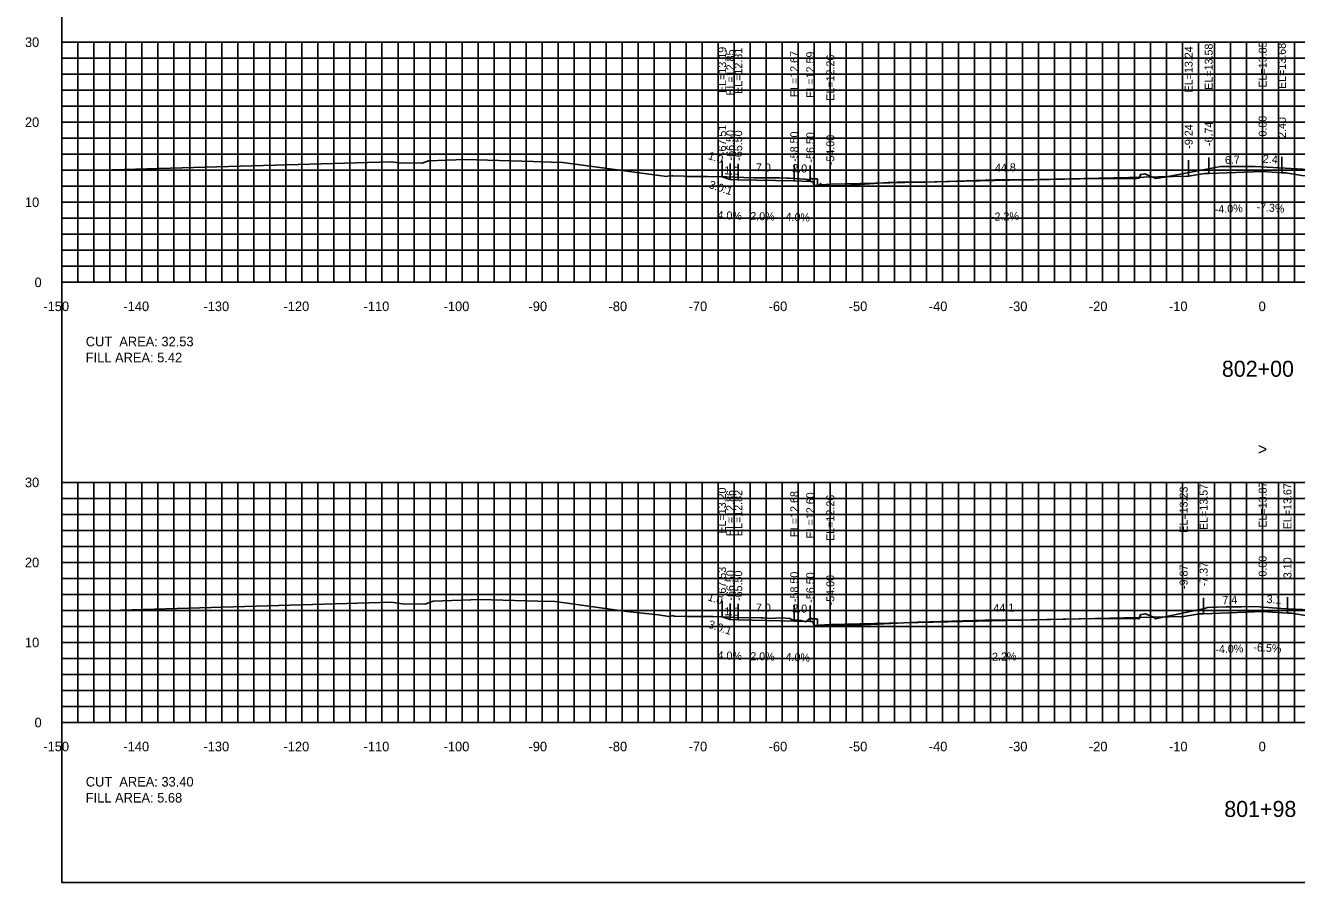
# Model space of a CAD drawing. Extents: x 1797419 to 1809236, y 248759 to 251512.
# Drawn here: x 1802476.5 to 1802635.2, y 250854.9 to 250962 of the extents above; entities that cross this region are included whole.
import ezdxf

# ---------------------------------------------------------------- set-up
doc = ezdxf.new("R2010")
doc.units = 0
for name, color, linetype in [('1', 7, 'Continuous'), ('10', 7, 'Continuous'), ('3', 7, 'Continuous'), ('31', 7, 'Continuous'), ('4', 7, 'Continuous'), ('60', 7, 'Continuous'), ('ANNO-TXT', 7, 'Continuous'), ('CL-CNST', 7, 'Continuous'), ('Level 62', 7, 'Continuous'), ('M-ROADS', 7, 'Continuous')]:
    doc.layers.add(name, color=color, linetype=linetype)

msp = doc.modelspace()

# ---------------------------------------------------------------- linework, layer by layer
for p, q in [((1802563.49, 250943.08), (1802563.49, 250945.08)), ((1802564.5, 250942.74), (1802564.5, 250944.74)), ((1802565.5, 250942.7), (1802565.5, 250944.7)), ((1802621.76, 250943.13), (1802621.76, 250945.13)), ((1802624.26, 250943.47), (1802624.26, 250945.47)), ((1802631, 250943.74), (1802631, 250945.74)), ((1802633.4, 250943.57), (1802633.4, 250945.57)), ((1802572.5, 250942.56), (1802572.5, 250944.56)), ((1802574.5, 250942.48), (1802574.5, 250944.48)), ((1802577, 250942.15), (1802577, 250944.15)), ((1802631, 250888.76), (1802631, 250890.76)), ((1802563.47, 250888.09), (1802563.47, 250890.09)), ((1802564.5, 250887.75), (1802564.5, 250889.75)), ((1802565.5, 250887.71), (1802565.5, 250889.71)), ((1802572.5, 250887.57), (1802572.5, 250889.57)), ((1802574.5, 250887.49), (1802574.5, 250889.49)), ((1802577, 250887.15), (1802577, 250889.15)), ((1802623.63, 250888.46), (1802623.63, 250890.46)), ((1802634.1, 250888.56), (1802634.1, 250890.56))]:
    msp.add_line(p, q)
msp.add_lwpolyline([(1802481, 250854.89), (1802781, 250854.89), (1802781, 251044.89), (1802481, 251044.89)], close=True)
at = {"layer": '60'}
for p, q in [((1802480.94, 250959.89), (1802481, 250959.89)), ((1802481, 250929.89), (1802481, 250959.89)), ((1802480.94, 250949.89), (1802481, 250949.89)), ((1802480.94, 250939.89), (1802481, 250939.89)), ((1802480.94, 250929.89), (1802481, 250929.89)), ((1802481, 250929.89), (1802781, 250929.89)), ((1802481, 250929.83), (1802481, 250929.89)), ((1802491, 250929.83), (1802491, 250929.89)), ((1802501, 250929.83), (1802501, 250929.89)), ((1802511, 250929.83), (1802511, 250929.89)), ((1802521, 250929.83), (1802521, 250929.89)), ((1802531, 250929.83), (1802531, 250929.89)), ((1802541, 250929.83), (1802541, 250929.89)), ((1802551, 250929.83), (1802551, 250929.89)), ((1802561, 250929.83), (1802561, 250929.89)), ((1802571, 250929.83), (1802571, 250929.89)), ((1802581, 250929.83), (1802581, 250929.89)), ((1802591, 250929.83), (1802591, 250929.89)), ((1802601, 250929.83), (1802601, 250929.89)), ((1802611, 250929.83), (1802611, 250929.89)), ((1802621, 250929.83), (1802621, 250929.89)), ((1802631, 250929.83), (1802631, 250929.89)), ((1802480.94, 250904.89), (1802481, 250904.89)), ((1802481, 250874.89), (1802481, 250904.89)), ((1802480.94, 250894.89), (1802481, 250894.89)), ((1802480.94, 250884.89), (1802481, 250884.89)), ((1802480.94, 250874.89), (1802481, 250874.89)), ((1802481, 250874.89), (1802781, 250874.89)), ((1802481, 250874.83), (1802481, 250874.89)), ((1802491, 250874.83), (1802491, 250874.89)), ((1802501, 250874.83), (1802501, 250874.89)), ((1802511, 250874.83), (1802511, 250874.89)), ((1802521, 250874.83), (1802521, 250874.89)), ((1802531, 250874.83), (1802531, 250874.89)), ((1802541, 250874.83), (1802541, 250874.89)), ((1802551, 250874.83), (1802551, 250874.89)), ((1802561, 250874.83), (1802561, 250874.89)), ((1802571, 250874.83), (1802571, 250874.89)), ((1802581, 250874.83), (1802581, 250874.89)), ((1802591, 250874.83), (1802591, 250874.89)), ((1802601, 250874.83), (1802601, 250874.89)), ((1802611, 250874.83), (1802611, 250874.89)), ((1802621, 250874.83), (1802621, 250874.89)), ((1802631, 250874.83), (1802631, 250874.89))]:
    msp.add_line(p, q, dxfattribs=at)
at = {"layer": 'CL-CNST'}
for points in [[(1802563.49, 250943.08), (1802564.5, 250942.74), (1802565.5, 250942.7), (1802572.5, 250942.56), (1802574.5, 250942.48), (1802574.83, 250942.48), (1802575, 250941.98), (1802577, 250942.15), (1802621.76, 250943.13), (1802623.76, 250943.47), (1802624.26, 250943.47), (1802631, 250943.74), (1802633.4, 250943.57), (1802633.9, 250943.57), (1802635.9, 250943.23), (1802697, 250941.88), (1802699, 250941.72), (1802699.17, 250942.22), (1802699.5, 250942.22), (1802701.5, 250942.3), (1802706.5, 250942.4), (1802707.5, 250942.44), (1802709.18, 250943)], [(1802563.47, 250888.09), (1802564.5, 250887.75), (1802565.5, 250887.71), (1802572.5, 250887.57), (1802574.5, 250887.49), (1802574.83, 250887.49), (1802575, 250886.99), (1802577, 250887.15), (1802621.13, 250888.12), (1802623.13, 250888.46), (1802623.63, 250888.46), (1802631, 250888.76), (1802634.1, 250888.56), (1802634.6, 250888.56), (1802636.6, 250888.22), (1802697, 250886.89), (1802699, 250886.72), (1802699.17, 250887.22), (1802699.5, 250887.22), (1802701.5, 250887.3), (1802706.5, 250887.4), (1802707.5, 250887.44), (1802709.18, 250888.01)]]:
    msp.add_lwpolyline(points, dxfattribs=at)
at = {"layer": 'Level 62'}
for p, q in [((1802481, 250959.89), (1802781, 250959.89)), ((1802481, 250929.89), (1802481, 250959.89)), ((1802483, 250929.89), (1802483, 250959.89)), ((1802485, 250929.89), (1802485, 250959.89)), ((1802487, 250929.89), (1802487, 250959.89)), ((1802489, 250929.89), (1802489, 250959.89)), ((1802491, 250929.89), (1802491, 250959.89)), ((1802493, 250929.89), (1802493, 250959.89)), ((1802495, 250929.89), (1802495, 250959.89)), ((1802497, 250929.89), (1802497, 250959.89)), ((1802499, 250929.89), (1802499, 250959.89)), ((1802501, 250929.89), (1802501, 250959.89)), ((1802503, 250929.89), (1802503, 250959.89)), ((1802505, 250929.89), (1802505, 250959.89)), ((1802507, 250929.89), (1802507, 250959.89)), ((1802509, 250929.89), (1802509, 250959.89)), ((1802511, 250929.89), (1802511, 250959.89)), ((1802513, 250929.89), (1802513, 250959.89)), ((1802515, 250929.89), (1802515, 250959.89)), ((1802517, 250929.89), (1802517, 250959.89)), ((1802519, 250929.89), (1802519, 250959.89)), ((1802521, 250929.89), (1802521, 250959.89)), ((1802523, 250929.89), (1802523, 250959.89)), ((1802525, 250929.89), (1802525, 250959.89)), ((1802527, 250929.89), (1802527, 250959.89)), ((1802529, 250929.89), (1802529, 250959.89)), ((1802531, 250929.89), (1802531, 250959.89)), ((1802533, 250929.89), (1802533, 250959.89)), ((1802535, 250929.89), (1802535, 250959.89)), ((1802537, 250929.89), (1802537, 250959.89)), ((1802539, 250929.89), (1802539, 250959.89)), ((1802541, 250929.89), (1802541, 250959.89)), ((1802543, 250929.89), (1802543, 250959.89)), ((1802545, 250929.89), (1802545, 250959.89)), ((1802547, 250929.89), (1802547, 250959.89)), ((1802549, 250929.89), (1802549, 250959.89)), ((1802551, 250929.89), (1802551, 250959.89)), ((1802553, 250929.89), (1802553, 250959.89)), ((1802555, 250929.89), (1802555, 250959.89)), ((1802557, 250929.89), (1802557, 250959.89)), ((1802559, 250929.89), (1802559, 250959.89)), ((1802561, 250929.89), (1802561, 250959.89)), ((1802563, 250929.89), (1802563, 250959.89)), ((1802565, 250929.89), (1802565, 250959.89)), ((1802567, 250929.89), (1802567, 250959.89)), ((1802569, 250929.89), (1802569, 250959.89)), ((1802571, 250929.89), (1802571, 250959.89)), ((1802573, 250929.89), (1802573, 250959.89)), ((1802575, 250929.89), (1802575, 250959.89)), ((1802577, 250929.89), (1802577, 250959.89)), ((1802579, 250929.89), (1802579, 250959.89)), ((1802581, 250929.89), (1802581, 250959.89)), ((1802583, 250929.89), (1802583, 250959.89)), ((1802585, 250929.89), (1802585, 250959.89)), ((1802587, 250929.89), (1802587, 250959.89)), ((1802589, 250929.89), (1802589, 250959.89)), ((1802591, 250929.89), (1802591, 250959.89)), ((1802593, 250929.89), (1802593, 250959.89)), ((1802595, 250929.89), (1802595, 250959.89)), ((1802597, 250929.89), (1802597, 250959.89)), ((1802599, 250929.89), (1802599, 250959.89)), ((1802601, 250929.89), (1802601, 250959.89)), ((1802603, 250929.89), (1802603, 250959.89)), ((1802605, 250929.89), (1802605, 250959.89)), ((1802607, 250929.89), (1802607, 250959.89)), ((1802609, 250929.89), (1802609, 250959.89)), ((1802611, 250929.89), (1802611, 250959.89)), ((1802613, 250929.89), (1802613, 250959.89)), ((1802615, 250929.89), (1802615, 250959.89)), ((1802617, 250929.89), (1802617, 250959.89)), ((1802619, 250929.89), (1802619, 250959.89)), ((1802621, 250929.89), (1802621, 250959.89)), ((1802623, 250929.89), (1802623, 250959.89)), ((1802625, 250929.89), (1802625, 250959.89)), ((1802627, 250929.89), (1802627, 250959.89)), ((1802629, 250929.89), (1802629, 250959.89)), ((1802631, 250929.89), (1802631, 250959.89)), ((1802633, 250929.89), (1802633, 250959.89)), ((1802635, 250929.89), (1802635, 250959.89)), ((1802481, 250957.89), (1802781, 250957.89)), ((1802481, 250955.89), (1802781, 250955.89)), ((1802481, 250953.89), (1802781, 250953.89)), ((1802481, 250951.89), (1802781, 250951.89)), ((1802481, 250949.89), (1802781, 250949.89)), ((1802481, 250947.89), (1802781, 250947.89)), ((1802481, 250945.89), (1802781, 250945.89)), ((1802481, 250943.89), (1802781, 250943.89)), ((1802481, 250941.89), (1802781, 250941.89)), ((1802481, 250939.89), (1802781, 250939.89)), ((1802481, 250937.89), (1802781, 250937.89)), ((1802481, 250935.89), (1802781, 250935.89)), ((1802481, 250933.89), (1802781, 250933.89)), ((1802481, 250931.89), (1802781, 250931.89)), ((1802481, 250929.89), (1802781, 250929.89)), ((1802481, 250904.89), (1802781, 250904.89)), ((1802481, 250874.89), (1802481, 250904.89)), ((1802483, 250874.89), (1802483, 250904.89)), ((1802485, 250874.89), (1802485, 250904.89)), ((1802487, 250874.89), (1802487, 250904.89)), ((1802489, 250874.89), (1802489, 250904.89)), ((1802491, 250874.89), (1802491, 250904.89)), ((1802493, 250874.89), (1802493, 250904.89)), ((1802495, 250874.89), (1802495, 250904.89)), ((1802497, 250874.89), (1802497, 250904.89)), ((1802499, 250874.89), (1802499, 250904.89)), ((1802501, 250874.89), (1802501, 250904.89)), ((1802503, 250874.89), (1802503, 250904.89)), ((1802505, 250874.89), (1802505, 250904.89)), ((1802507, 250874.89), (1802507, 250904.89)), ((1802509, 250874.89), (1802509, 250904.89)), ((1802511, 250874.89), (1802511, 250904.89)), ((1802513, 250874.89), (1802513, 250904.89)), ((1802515, 250874.89), (1802515, 250904.89)), ((1802517, 250874.89), (1802517, 250904.89)), ((1802519, 250874.89), (1802519, 250904.89)), ((1802521, 250874.89), (1802521, 250904.89)), ((1802523, 250874.89), (1802523, 250904.89)), ((1802525, 250874.89), (1802525, 250904.89)), ((1802527, 250874.89), (1802527, 250904.89)), ((1802529, 250874.89), (1802529, 250904.89)), ((1802531, 250874.89), (1802531, 250904.89)), ((1802533, 250874.89), (1802533, 250904.89)), ((1802535, 250874.89), (1802535, 250904.89)), ((1802537, 250874.89), (1802537, 250904.89)), ((1802539, 250874.89), (1802539, 250904.89)), ((1802541, 250874.89), (1802541, 250904.89)), ((1802543, 250874.89), (1802543, 250904.89)), ((1802545, 250874.89), (1802545, 250904.89)), ((1802547, 250874.89), (1802547, 250904.89)), ((1802549, 250874.89), (1802549, 250904.89)), ((1802551, 250874.89), (1802551, 250904.89)), ((1802553, 250874.89), (1802553, 250904.89)), ((1802555, 250874.89), (1802555, 250904.89)), ((1802557, 250874.89), (1802557, 250904.89)), ((1802559, 250874.89), (1802559, 250904.89)), ((1802561, 250874.89), (1802561, 250904.89)), ((1802563, 250874.89), (1802563, 250904.89)), ((1802565, 250874.89), (1802565, 250904.89)), ((1802567, 250874.89), (1802567, 250904.89)), ((1802569, 250874.89), (1802569, 250904.89)), ((1802571, 250874.89), (1802571, 250904.89)), ((1802573, 250874.89), (1802573, 250904.89)), ((1802575, 250874.89), (1802575, 250904.89)), ((1802577, 250874.89), (1802577, 250904.89)), ((1802579, 250874.89), (1802579, 250904.89)), ((1802581, 250874.89), (1802581, 250904.89)), ((1802583, 250874.89), (1802583, 250904.89)), ((1802585, 250874.89), (1802585, 250904.89)), ((1802587, 250874.89), (1802587, 250904.89)), ((1802589, 250874.89), (1802589, 250904.89)), ((1802591, 250874.89), (1802591, 250904.89)), ((1802593, 250874.89), (1802593, 250904.89)), ((1802595, 250874.89), (1802595, 250904.89)), ((1802597, 250874.89), (1802597, 250904.89)), ((1802599, 250874.89), (1802599, 250904.89)), ((1802601, 250874.89), (1802601, 250904.89)), ((1802603, 250874.89), (1802603, 250904.89)), ((1802605, 250874.89), (1802605, 250904.89)), ((1802607, 250874.89), (1802607, 250904.89)), ((1802609, 250874.89), (1802609, 250904.89)), ((1802611, 250874.89), (1802611, 250904.89)), ((1802613, 250874.89), (1802613, 250904.89)), ((1802615, 250874.89), (1802615, 250904.89)), ((1802617, 250874.89), (1802617, 250904.89)), ((1802619, 250874.89), (1802619, 250904.89)), ((1802621, 250874.89), (1802621, 250904.89)), ((1802623, 250874.89), (1802623, 250904.89)), ((1802625, 250874.89), (1802625, 250904.89)), ((1802627, 250874.89), (1802627, 250904.89)), ((1802629, 250874.89), (1802629, 250904.89)), ((1802631, 250874.89), (1802631, 250904.89)), ((1802633, 250874.89), (1802633, 250904.89)), ((1802635, 250874.89), (1802635, 250904.89)), ((1802481, 250902.89), (1802781, 250902.89)), ((1802481, 250900.89), (1802781, 250900.89)), ((1802481, 250898.89), (1802781, 250898.89)), ((1802481, 250896.89), (1802781, 250896.89)), ((1802481, 250894.89), (1802781, 250894.89)), ((1802481, 250892.89), (1802781, 250892.89)), ((1802481, 250890.89), (1802781, 250890.89)), ((1802481, 250888.89), (1802781, 250888.89)), ((1802481, 250886.89), (1802781, 250886.89)), ((1802481, 250884.89), (1802781, 250884.89)), ((1802481, 250882.89), (1802781, 250882.89)), ((1802481, 250880.89), (1802781, 250880.89)), ((1802481, 250878.89), (1802781, 250878.89)), ((1802481, 250876.89), (1802781, 250876.89)), ((1802481, 250874.89), (1802781, 250874.89))]:
    msp.add_line(p, q, dxfattribs=at)
at = {"layer": 'M-ROADS'}
for points in [[(1802484.41, 250943.84), (1802522.14, 250944.95), (1802523.48, 250944.77), (1802525.11, 250944.82), (1802526, 250944.77), (1802526.8, 250945.07), (1802531.39, 250945.24), (1802539.9, 250944.98), (1802542.16, 250944.91), (1802543.57, 250944.87), (1802555.63, 250943.22), (1802556.24, 250943.16), (1802556.45, 250943.12), (1802557.07, 250943.25), (1802557.16, 250943.17), (1802557.21, 250943.19), (1802557.25, 250943.19), (1802557.31, 250943.19), (1802558.74, 250943.13), (1802558.96, 250943.12), (1802560.46, 250943.12), (1802561.66, 250943.12), (1802564.07, 250943.07), (1802564.89, 250943.01), (1802567.48, 250942.95), (1802568.09, 250942.95), (1802570.33, 250942.95), (1802570.44, 250942.94), (1802570.59, 250942.95), (1802571.53, 250942.9), (1802571.65, 250942.89), (1802571.85, 250942.9), (1802573.79, 250942.78), (1802574.05, 250942.72), (1802574.08, 250942.77), (1802574.3, 250942.62), (1802574.33, 250942.71), (1802574.35, 250942.73), (1802574.37, 250942.76), (1802574.38, 250942.79), (1802574.39, 250942.8), (1802574.39, 250942.8), (1802574.4, 250942.82), (1802574.4, 250942.82), (1802574.41, 250942.83), (1802574.41, 250942.83), (1802574.42, 250942.83), (1802574.45, 250942.88), (1802574.73, 250942.85), (1802574.77, 250942.77), (1802574.89, 250942.83), (1802575.34, 250942.82), (1802575.39, 250942.69), (1802575.39, 250941.97), (1802575.39, 250941.97), (1802575.4, 250941.97), (1802575.42, 250941.97), (1802575.5, 250941.96), (1802575.78, 250942.25), (1802575.85, 250941.96), (1802576.85, 250941.95), (1802578.37, 250941.96), (1802584.22, 250942.35), (1802585.37, 250942.4), (1802587.5, 250942.4), (1802589.1, 250942.4), (1802594.03, 250942.57), (1802597.58, 250942.69), (1802599.43, 250942.69), (1802601.92, 250942.69), (1802601.98, 250942.69), (1802602.38, 250942.7), (1802610.17, 250942.87), (1802611.61, 250942.88), (1802612.4, 250942.88), (1802612.58, 250942.88), (1802612.89, 250942.86), (1802612.97, 250942.86), (1802614.05, 250942.87), (1802614.49, 250942.87), (1802615.02, 250942.87), (1802615.09, 250942.87), (1802615.11, 250942.88), (1802615.12, 250942.98), (1802615.12, 250942.88), (1802615.12, 250942.87), (1802615.13, 250942.87), (1802615.13, 250942.88), (1802615.14, 250942.88), (1802615.24, 250942.86), (1802615.58, 250942.92), (1802615.73, 250943.37), (1802615.8, 250943.37), (1802615.81, 250943.3), (1802615.81, 250943.36), (1802615.82, 250943.33), (1802615.89, 250943.36), (1802616.29, 250943.44), (1802617.67, 250942.86), (1802618.73, 250943.02), (1802625.75, 250944.36), (1802627.21, 250944.36), (1802629.15, 250944.36), (1802630.05, 250944.35), (1802639.01, 250943.86)], [(1802486.96, 250888.87), (1802522.2, 250889.91), (1802523.83, 250889.68), (1802525.21, 250889.72), (1802526.36, 250889.67), (1802527.38, 250890.04), (1802533.27, 250890.27), (1802538.95, 250890.09), (1802540.46, 250890.05), (1802542.63, 250889.99), (1802551.6, 250888.76), (1802555.52, 250888.35), (1802556.84, 250888.14), (1802557.35, 250888.24), (1802557.43, 250888.18), (1802557.47, 250888.19), (1802557.51, 250888.19), (1802557.56, 250888.19), (1802559.18, 250888.12), (1802559.58, 250888.12), (1802562.36, 250888.12), (1802564.34, 250888.07), (1802565.01, 250888.03), (1802568.37, 250887.95), (1802568.41, 250887.95), (1802568.55, 250887.95), (1802569.56, 250887.89), (1802570.15, 250887.92), (1802570.93, 250887.95), (1802571.91, 250887.89), (1802571.99, 250887.89), (1802572.16, 250887.76), (1802573.34, 250887.62), (1802573.93, 250887.45), (1802574.05, 250887.59), (1802574.46, 250887.89), (1802574.73, 250887.87), (1802574.77, 250887.8), (1802574.87, 250887.85), (1802575.35, 250887.84), (1802575.39, 250887.73), (1802575.39, 250887.1), (1802575.64, 250886.97), (1802577.71, 250886.97), (1802578.03, 250886.97), (1802578.24, 250886.97), (1802579.05, 250887.02), (1802582, 250887.14), (1802587.89, 250887.41), (1802588.01, 250887.41), (1802596.34, 250887.68), (1802597.61, 250887.71), (1802599.19, 250887.69), (1802599.77, 250887.69), (1802600.21, 250887.69), (1802602.09, 250887.73), (1802608.1, 250887.84), (1802610.19, 250887.88), (1802612.15, 250887.89), (1802612.39, 250887.89), (1802612.78, 250887.88), (1802613, 250887.87), (1802613.44, 250887.87), (1802614.86, 250887.86), (1802615.05, 250887.86), (1802615.11, 250887.89), (1802615.12, 250887.97), (1802615.12, 250887.89), (1802615.12, 250887.89), (1802615.13, 250887.88), (1802615.15, 250887.89), (1802615.16, 250887.89), (1802615.48, 250887.85), (1802615.58, 250887.86), (1802615.75, 250888.38), (1802615.8, 250888.38), (1802615.81, 250888.33), (1802615.81, 250888.37), (1802615.82, 250888.35), (1802615.88, 250888.37), (1802616.35, 250888.47), (1802617.36, 250888.04), (1802617.62, 250887.85), (1802623.72, 250889.13), (1802624.13, 250889.25), (1802626.43, 250889.36), (1802627.55, 250889.36), (1802628.39, 250889.36), (1802630.06, 250889.37), (1802633.31, 250889.13), (1802636.88, 250888.96)]]:
    msp.add_lwpolyline(points, dxfattribs=at)

# ---------------------------------------------------------------- texts
for p in [(1802561.75, 250941.7), (1802561.67, 250886.76)]:
    msp.add_text('3.0:1', height=1, rotation=341.5651).set_placement(p)
at = {"layer": '1'}
for s, p in [('802+00', (1802625.91, 250918.09)), ('801+98', (1802626.21, 250863.09))]:
    msp.add_text(s, height=2, dxfattribs=at).set_placement(p)
at = {"layer": '10'}
for s, p in [('-150', (1802478.7, 250926.29)), ('-140', (1802488.7, 250926.29)), ('-130', (1802498.7, 250926.29)), ('-120', (1802508.7, 250926.29)), ('-110', (1802518.7, 250926.29)), ('-100', (1802528.7, 250926.29)), ('-90', (1802539.3, 250926.29)), ('-80', (1802549.3, 250926.29)), ('-70', (1802559.3, 250926.29)), ('-60', (1802569.3, 250926.29)), ('-50', (1802579.3, 250926.29)), ('-40', (1802589.3, 250926.29)), ('-30', (1802599.3, 250926.29)), ('-20', (1802609.3, 250926.29)), ('-10', (1802619.3, 250926.29)), ('0', (1802630.5, 250926.29)), ('-150', (1802478.7, 250871.29)), ('-140', (1802488.7, 250871.29)), ('-130', (1802498.7, 250871.29)), ('-120', (1802508.7, 250871.29)), ('-110', (1802518.7, 250871.29)), ('-100', (1802528.7, 250871.29)), ('-90', (1802539.3, 250871.29)), ('-80', (1802549.3, 250871.29)), ('-70', (1802559.3, 250871.29)), ('-60', (1802569.3, 250871.29)), ('-50', (1802579.3, 250871.29)), ('-40', (1802589.3, 250871.29)), ('-30', (1802599.3, 250871.29)), ('-20', (1802609.3, 250871.29)), ('-10', (1802619.3, 250871.29)), ('0', (1802630.5, 250871.29))]:
    msp.add_text(s, height=1.2, dxfattribs=at).set_placement(p)
at = {"layer": '3'}
for s, p in [('EL=13.19', (1802563.99, 250953.55)), ('EL=12.81', (1802566, 250953.43)), ('EL=13.24', (1802622.26, 250953.61)), ('EL=13.58', (1802624.76, 250953.95)), ('EL=13.85', (1802631.5, 250954.21)), ('EL=13.68', (1802633.9, 250954.04)), ('EL=12.85', (1802565, 250953.21)), ('EL=12.67', (1802573, 250953.03)), ('EL=12.59', (1802575, 250952.95)), ('EL=12.26', (1802577.5, 250952.57)), ('-67.51', (1802563.99, 250945.79)), ('-9.24', (1802622.26, 250946.58)), ('-6.74', (1802624.76, 250946.92)), ('0.00', (1802631.5, 250948.1)), ('2.40', (1802633.9, 250947.93)), ('-66.50', (1802565, 250945.12)), ('-65.50', (1802566, 250945.08)), ('-58.50', (1802573, 250944.94)), ('-56.50', (1802575, 250944.86)), ('-54.00', (1802577.5, 250944.53)), ('EL=13.20', (1802563.97, 250898.49)), ('EL=12.86', (1802565, 250898.17)), ('EL=12.82', (1802566, 250898.18)), ('EL=12.68', (1802573, 250898.04)), ('EL=12.60', (1802575, 250897.88)), ('EL=13.23', (1802621.63, 250898.6)), ('EL=13.57', (1802624.13, 250898.94)), ('EL=13.87', (1802631.5, 250899.23)), ('EL=13.67', (1802634.6, 250899.03)), ('EL=12.26', (1802577.5, 250897.58)), ('0.00', (1802631.5, 250893.12)), ('-67.53', (1802563.97, 250890.55)), ('-9.87', (1802621.63, 250891.57)), ('-7.37', (1802624.13, 250891.91)), ('3.10', (1802634.6, 250892.92)), ('-66.50', (1802565, 250890.12)), ('-65.50', (1802566, 250890.08)), ('-58.50', (1802573, 250889.94)), ('-56.50', (1802575, 250889.86)), ('-54.00', (1802577.5, 250889.53))]:
    msp.add_text(s, height=1, rotation=90, dxfattribs=at).set_placement(p)
at = {"layer": '31'}
for s, p in [('30', (1802476.4, 250959.29)), ('20', (1802476.4, 250949.29)), ('10', (1802476.4, 250939.29)), ('0', (1802477.6, 250929.29)), ('30', (1802476.4, 250904.29)), ('20', (1802476.4, 250894.29)), ('10', (1802476.4, 250884.29)), ('0', (1802477.6, 250874.29))]:
    msp.add_text(s, height=1.2, dxfattribs=at).set_placement(p)
at = {"layer": '4'}
for s, rotation, p in [('1.0', 341.5651, (1802561.65, 250945.31)), ('7.0', 358.8542, (1802567.7, 250943.76)), ('44.8', 1.2603, (1802597.58, 250943.7)), ('6.7', 2.2906, (1802626.31, 250944.66)), ('2.4', 355.849, (1802631, 250944.85)), ('1.0', 357.7094, (1802563.73, 250943.39)), ('2.0', 357.7094, (1802572.23, 250943.67)), ('4.0%', 357.7094, (1802562.89, 250937.8)), ('2.0%', 358.8542, (1802566.99, 250937.67)), ('4.0%', 357.7094, (1802571.39, 250937.6)), ('-2.2%', 1.2603, (1802597.08, 250937.59)), ('-4.0%', 2.2906, (1802625.04, 250938.52)), ('-7.3%', 355.849, (1802630.2, 250938.84)), ('1.0', 341.5651, (1802561.6, 250890.18)), ('7.4', 2.2906, (1802625.99, 250889.66)), ('3.1', 356.2907, (1802631.47, 250889.83)), ('1.0', 357.7094, (1802563.73, 250888.3)), ('7.0', 358.8542, (1802567.7, 250888.76)), ('2.0', 357.7094, (1802572.23, 250888.68)), ('44.1', 1.2603, (1802597.39, 250888.7)), ('-4.0%', 2.2906, (1802625.11, 250883.52)), ('-6.5%', 356.2907, (1802629.82, 250883.83)), ('4.0%', 357.7094, (1802562.89, 250882.81)), ('2.0%', 358.8542, (1802566.99, 250882.68)), ('4.0%', 357.7094, (1802571.39, 250882.61)), ('-2.2%', 1.2603, (1802596.77, 250882.59))]:
    msp.add_text(s, height=1, rotation=rotation, dxfattribs=at).set_placement(p)
at = {"layer": '60'}
for s, height, p in [('-', 0.0001, (1802481, 250929.89)), ('>', 1.5, (1802630.39, 250908.31)), ('-', 0.0001, (1802481, 250874.89))]:
    msp.add_text(s, height=height, dxfattribs=at).set_placement(p)
at = {"layer": 'ANNO-TXT'}
for s, p in [('CUT  AREA: 32.53', (1802484, 250921.89)), ('FILL AREA: 5.42', (1802484, 250919.89)), ('CUT  AREA: 33.40', (1802484, 250866.89)), ('FILL AREA: 5.68', (1802484, 250864.89))]:
    msp.add_text(s, height=1.2, dxfattribs=at).set_placement(p)

doc.saveas('drawing.dxf')
